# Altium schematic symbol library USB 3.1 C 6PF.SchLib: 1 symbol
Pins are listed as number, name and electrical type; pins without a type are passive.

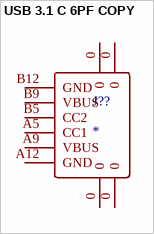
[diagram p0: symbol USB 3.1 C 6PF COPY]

## USB 3.1 C 6PF COPY
designator J??
footprint USB-C-SMD_TYPE-C-USB-13
pins: 0, 0, 0, 0, A5 CC1, A9 VBUS, A12 GND, B5 CC2, B9 VBUS, B12 GND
